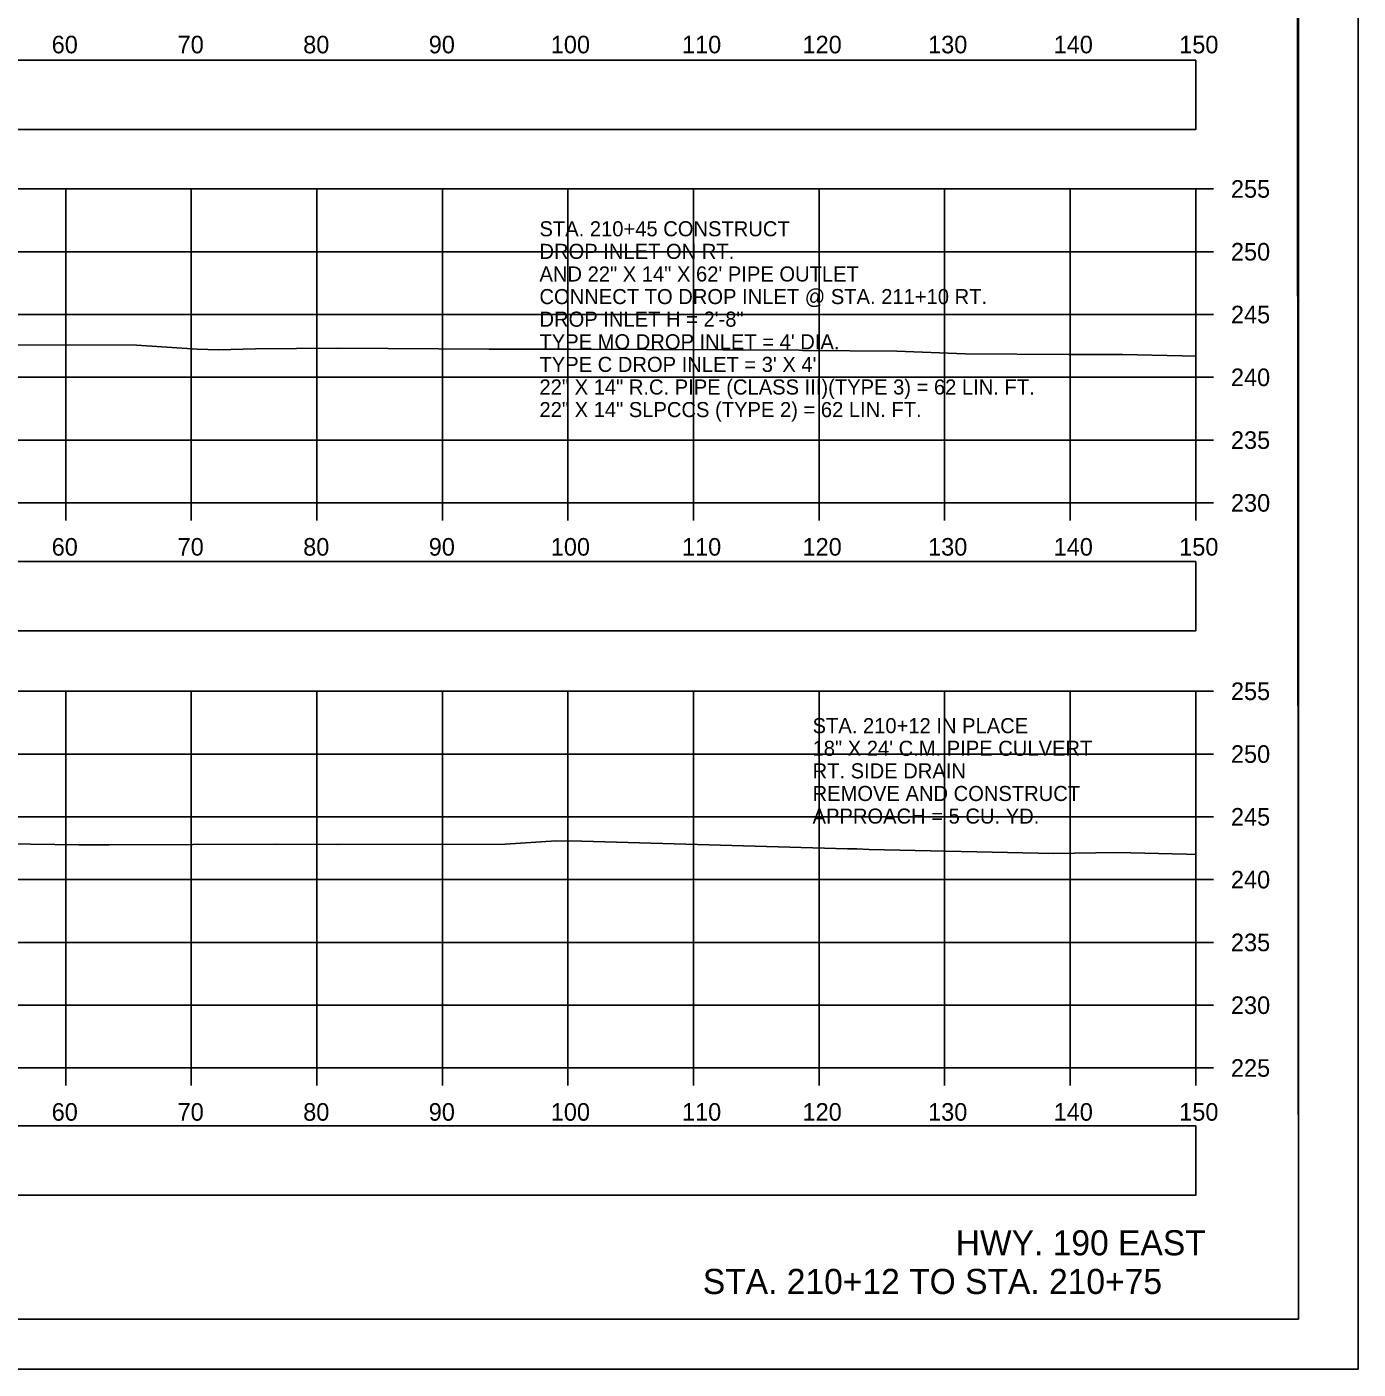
# Model space of a CAD drawing. Extents: x 1369627 to 1374022, y 380035 to 398173.
# Drawn here: x 1372155.4 to 1372261.5, y 382172.2 to 382279 of the extents above; entities that cross this region are included whole.
import ezdxf

# ---------------------------------------------------------------- set-up
doc = ezdxf.new("R2010")
doc.units = 0
for name, color, linetype in [('Default', 7, 'Continuous'), ('R_Axis', 7, 'Continuous'), ('R_Axis Annot', 7, 'Continuous'), ('R_Border', 7, 'Continuous'), ('R_Draft', 7, 'Continuous'), ('R_Exist Surface', 7, 'Continuous'), ('R_Grid', 7, 'Continuous'), ('R_No Plot', 7, 'Continuous'), ('R_Water', 7, 'Continuous'), ('R_Water Annot', 7, 'Continuous')]:
    doc.layers.add(name, color=color, linetype=linetype)

msp = doc.modelspace()

# ---------------------------------------------------------------- linework, layer by layer
at = {"layer": 'Default'}
for points in [[(1371948.53, 382270.87), (1372248.53, 382270.87), (1372248.53, 382276.39), (1371948.53, 382276.39)], [(1371948.53, 382230.95), (1372248.53, 382230.95), (1372248.53, 382236.47), (1371948.53, 382236.47)], [(1371948.53, 382186), (1372248.53, 382186), (1372248.53, 382191.52), (1371948.53, 382191.52)]]:
    msp.add_lwpolyline(points, close=True, dxfattribs=at)
at = {"layer": 'R_Axis'}
for p, q in [((1372248.53, 382241.14), (1372248.53, 382266.14)), ((1372249.93, 382266.14), (1372248.53, 382266.14)), ((1372249.93, 382261.14), (1372248.53, 382261.14)), ((1372249.93, 382256.14), (1372248.53, 382256.14)), ((1372249.93, 382251.14), (1372248.53, 382251.14)), ((1372249.93, 382246.14), (1372248.53, 382246.14)), ((1371948.53, 382241.14), (1372248.53, 382241.14)), ((1372158.53, 382239.74), (1372158.53, 382241.14)), ((1372168.53, 382239.74), (1372168.53, 382241.14)), ((1372178.53, 382239.74), (1372178.53, 382241.14)), ((1372188.53, 382239.74), (1372188.53, 382241.14)), ((1372198.53, 382239.74), (1372198.53, 382241.14)), ((1372208.53, 382239.74), (1372208.53, 382241.14)), ((1372218.53, 382239.74), (1372218.53, 382241.14)), ((1372228.53, 382239.74), (1372228.53, 382241.14)), ((1372238.53, 382239.74), (1372238.53, 382241.14)), ((1372248.53, 382239.74), (1372248.53, 382241.14)), ((1372249.93, 382241.14), (1372248.53, 382241.14)), ((1372248.53, 382196.14), (1372248.53, 382226.14)), ((1372249.93, 382226.14), (1372248.53, 382226.14)), ((1372249.93, 382221.14), (1372248.53, 382221.14)), ((1372249.93, 382216.14), (1372248.53, 382216.14)), ((1372249.93, 382211.14), (1372248.53, 382211.14)), ((1372249.93, 382206.14), (1372248.53, 382206.14)), ((1372249.93, 382201.14), (1372248.53, 382201.14)), ((1371948.53, 382196.14), (1372248.53, 382196.14)), ((1372158.53, 382194.74), (1372158.53, 382196.14)), ((1372168.53, 382194.74), (1372168.53, 382196.14)), ((1372178.53, 382194.74), (1372178.53, 382196.14)), ((1372188.53, 382194.74), (1372188.53, 382196.14)), ((1372198.53, 382194.74), (1372198.53, 382196.14)), ((1372208.53, 382194.74), (1372208.53, 382196.14)), ((1372218.53, 382194.74), (1372218.53, 382196.14)), ((1372228.53, 382194.74), (1372228.53, 382196.14)), ((1372238.53, 382194.74), (1372238.53, 382196.14)), ((1372248.53, 382194.74), (1372248.53, 382196.14)), ((1372249.93, 382196.14), (1372248.53, 382196.14))]:
    msp.add_line(p, q, dxfattribs=at)
at = {"layer": 'R_Border'}
for q in [(1372256.71, 382381.6), (1371940.53, 382176.14)]:
    msp.add_line((1372256.71, 382176.14), q, dxfattribs=at)
at = {"layer": 'R_Exist Surface'}
for points in [[(1372154.24, 382253.73), (1372164.17, 382253.7), (1372169, 382253.39), (1372170.7, 382253.33), (1372173.63, 382253.4), (1372180.18, 382253.46), (1372192.26, 382253.37), (1372198.72, 382253.39), (1372216.95, 382253.29), (1372217.2, 382253.28), (1372224.72, 382253.21), (1372230.17, 382253.02), (1372238.43, 382252.95), (1372242.7, 382252.96), (1372247.44, 382252.84), (1372248.53, 382252.82)], [(1372140.34, 382214.18), (1372159.58, 382213.91), (1372162, 382213.92), (1372175.31, 382213.96), (1372180.19, 382213.94), (1372193.53, 382213.97), (1372197.6, 382214.22), (1372199.64, 382214.19), (1372220.79, 382213.59), (1372221.18, 382213.6), (1372221.27, 382213.6), (1372221.54, 382213.6), (1372222.51, 382213.55), (1372237.19, 382213.23), (1372242.23, 382213.29), (1372247.78, 382213.16), (1372248.53, 382213.14)]]:
    msp.add_lwpolyline(points, dxfattribs=at)
at = {"layer": 'R_Grid'}
for p, q in [((1371948.53, 382266.14), (1372248.53, 382266.14)), ((1372158.53, 382241.14), (1372158.53, 382266.14)), ((1372168.53, 382241.14), (1372168.53, 382266.14)), ((1372178.53, 382241.14), (1372178.53, 382266.14)), ((1372188.53, 382241.14), (1372188.53, 382266.14)), ((1372198.53, 382241.14), (1372198.53, 382266.14)), ((1372208.53, 382241.14), (1372208.53, 382266.14)), ((1372218.53, 382241.14), (1372218.53, 382266.14)), ((1372228.53, 382241.14), (1372228.53, 382266.14)), ((1372238.53, 382241.14), (1372238.53, 382266.14)), ((1372248.53, 382241.14), (1372248.53, 382266.14)), ((1371948.53, 382261.14), (1372248.53, 382261.14)), ((1371948.53, 382256.14), (1372248.53, 382256.14)), ((1371948.53, 382251.14), (1372248.53, 382251.14)), ((1371948.53, 382246.14), (1372248.53, 382246.14)), ((1371948.53, 382241.14), (1372248.53, 382241.14)), ((1371948.53, 382226.14), (1372248.53, 382226.14)), ((1372158.53, 382196.14), (1372158.53, 382226.14)), ((1372168.53, 382196.14), (1372168.53, 382226.14)), ((1372178.53, 382196.14), (1372178.53, 382226.14)), ((1372188.53, 382196.14), (1372188.53, 382226.14)), ((1372198.53, 382196.14), (1372198.53, 382226.14)), ((1372208.53, 382196.14), (1372208.53, 382226.14)), ((1372218.53, 382196.14), (1372218.53, 382226.14)), ((1372228.53, 382196.14), (1372228.53, 382226.14)), ((1372238.53, 382196.14), (1372238.53, 382226.14)), ((1372248.53, 382196.14), (1372248.53, 382226.14)), ((1371948.53, 382221.14), (1372248.53, 382221.14)), ((1371948.53, 382216.14), (1372248.53, 382216.14)), ((1371948.53, 382211.14), (1372248.53, 382211.14)), ((1371948.53, 382206.14), (1372248.53, 382206.14)), ((1371948.53, 382201.14), (1372248.53, 382201.14)), ((1371948.53, 382196.14), (1372248.53, 382196.14))]:
    msp.add_line(p, q, dxfattribs=at)
at = {"layer": 'R_No Plot'}
msp.add_line((1371928.13, 382172.16), (1372261.46, 382172.16), dxfattribs=at)
for points in [[(1371928.12, 382385.49), (1372261.46, 382385.49), (1372261.46, 382172.16), (1371928.12, 382172.16)], [(1372174.45, 382381.6), (1372194.07, 382381.6), (1372194.07, 382371.72), (1372210.18, 382371.72), (1372233.38, 382371.72), (1372233.38, 382339.05), (1372256.59, 382339.05), (1372256.71, 382176.14), (1371940.53, 382176.14), (1371940.53, 382381.6)]]:
    msp.add_lwpolyline(points, close=True, dxfattribs=at)

# ---------------------------------------------------------------- texts
at = {"layer": 'R_Axis Annot'}
for s, p in [('60', (1372157.41, 382276.94)), ('70', (1372167.44, 382276.94)), ('80', (1372177.44, 382276.94)), ('90', (1372187.44, 382276.94)), ('100', (1372197.16, 382276.94)), ('110', (1372207.61, 382276.94)), ('120', (1372217.21, 382276.94)), ('130', (1372227.21, 382276.94)), ('140', (1372237.21, 382276.94)), ('150', (1372247.21, 382276.94)), ('255', (1372251.33, 382265.44)), ('250', (1372251.33, 382260.44)), ('245', (1372251.33, 382255.44)), ('240', (1372251.33, 382250.44)), ('235', (1372251.33, 382245.44)), ('230', (1372251.33, 382240.44)), ('60', (1372157.41, 382236.94)), ('70', (1372167.44, 382236.94)), ('80', (1372177.44, 382236.94)), ('90', (1372187.44, 382236.94)), ('100', (1372197.16, 382236.94)), ('110', (1372207.61, 382236.94)), ('120', (1372217.21, 382236.94)), ('130', (1372227.21, 382236.94)), ('140', (1372237.21, 382236.94)), ('150', (1372247.21, 382236.94)), ('255', (1372251.33, 382225.44)), ('250', (1372251.33, 382220.44)), ('245', (1372251.33, 382215.44)), ('240', (1372251.33, 382210.44)), ('235', (1372251.33, 382205.44)), ('230', (1372251.33, 382200.44)), ('225', (1372251.33, 382195.44)), ('60', (1372157.41, 382191.94)), ('70', (1372167.44, 382191.94)), ('80', (1372177.44, 382191.94)), ('90', (1372187.44, 382191.94)), ('100', (1372197.16, 382191.94)), ('110', (1372207.61, 382191.94)), ('120', (1372217.21, 382191.94)), ('130', (1372227.21, 382191.94)), ('140', (1372237.21, 382191.94)), ('150', (1372247.21, 382191.94))]:
    msp.add_text(s, height=1.4, dxfattribs=at).set_placement(p)
at = {"layer": 'R_Draft'}
for s, p in [('HWY. 190 EAST', (1372229.41, 382181.22)), ('STA. 210+12 TO STA. 210+75', (1372209.27, 382178.14))]:
    msp.add_text(s, height=2, dxfattribs=at).set_placement(p)
at = {"layer": 'R_Water'}
for s, p in [('STA. 210+12 IN PLACE', (1372218.01, 382222.8)), ('18" X 24\' C.M. PIPE CULVERT', (1372218.01, 382221)), ('RT. SIDE DRAIN', (1372218.01, 382219.2)), ('REMOVE AND CONSTRUCT', (1372218.01, 382217.4)), ('APPROACH = 5 CU. YD.', (1372218.01, 382215.6))]:
    msp.add_text(s, height=1.2, dxfattribs=at).set_placement(p)
at = {"layer": 'R_Water Annot'}
for s, p in [('STA. 210+45 CONSTRUCT', (1372196.26, 382262.37)), ('DROP INLET ON RT.', (1372196.26, 382260.57)), ('AND 22" X 14" X 62\' PIPE OUTLET', (1372196.26, 382258.77)), ('CONNECT TO DROP INLET @ STA. 211+10 RT.', (1372196.26, 382256.97)), ('DROP INLET H = 2\'-8"', (1372196.26, 382255.17)), ("TYPE MO DROP INLET = 4' DIA.", (1372196.26, 382253.37)), ("TYPE C DROP INLET = 3' X 4'", (1372196.26, 382251.57)), ('22" X 14" R.C. PIPE (CLASS III)(TYPE 3) = 62 LIN. FT.', (1372196.26, 382249.77)), ('22" X 14" SLPCCS (TYPE 2) = 62 LIN. FT.', (1372196.26, 382247.97))]:
    msp.add_text(s, height=1.2, dxfattribs=at).set_placement(p)

doc.saveas('drawing.dxf')
